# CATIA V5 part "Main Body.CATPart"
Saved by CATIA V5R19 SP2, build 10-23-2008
Part number: Main Body
Definition: Main Body
Nomenclature: Main Body
Source: Unknown
Bounding box of the stored display mesh (mm): x -12.89 to 12.89, y -12.89 to 12.89, z -8.4 to 13.6
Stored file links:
  Z:\fausse table rondelle-20220905T211342Z-001\fausse table rondelle\Main Body.CATPart
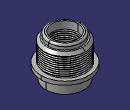
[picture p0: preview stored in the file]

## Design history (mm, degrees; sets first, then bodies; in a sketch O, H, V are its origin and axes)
AxisSystem1: origin (0, 0, 0), X (1, 0, 0), Y (0, 1, 0), Z (0, 0, 1)
Body1 "Main Body" (main body)
  Solid1: solid without history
